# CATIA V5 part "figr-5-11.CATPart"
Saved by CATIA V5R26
Part number: Part1
Bounding box of the stored display mesh (mm): x 0 to 150, y -70 to 70, z -150 to 69.804
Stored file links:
  D:\_Deepak\CATIA\CATIA V5-6R2016_Deepak\Resources\Part files\Partfiles\c05_catia_v5_6r2016_prt\figr-5-11.CATPart
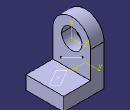
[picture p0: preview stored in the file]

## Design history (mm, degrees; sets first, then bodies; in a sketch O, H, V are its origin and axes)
Set1
  Sketch1 on face of Pad2, origin (0, 0, -100), H (1, 0, 0), V (0, 1, 0)
    point P1 (100, 0)
    coincidence: P1 H
  Sketch2 on face of Pad1, origin (50, 0, 0), H (0, 1, 0), V (0, 0, 1)
    line L1 (-40, -80) -> (40, -40)
  Plane1: type 1Line1Pt, RefPoint Sketch1, Line Sketch2
Body1 (main body)
  Sketch3 on yz-plane, origin (0, 0, 0), H (0, 1, 0), V (0, 0, 1)
    arc A1 centre (0, 0) radius 70 from (70, 0) to (-70, 0) ccw
    point P1 (70, 0)
    point P2 (-70, 0)
    line L1 (-70, 0) -> (-70, -150)
    line L2 (-70, -150) -> (70, -150)
    line L3 (70, -150) -> (70, 0)
    circle A2 centre (0, 0) radius 37.5
    radius A1 = 70
    radius A2 = 37.5
    distance O L2 = 150
    coincidence: P1 H, P2 H
    tangency: L1 A1, L3 A1
    horizontal: L2 H
  Pad1: profile Sketch3, direction (1, 0, 0), length 50
  Sketch4 on face of Pad1, origin (50, 0, 0), H (0, 1, 0), V (0, 0, 1)
    line L1 (-70, -150) -> (70, -150)
    line L2 (70, -150) -> (70, -100)
    line L3 (70, -100) -> (-70, -100)
    line L4 (-70, -100) -> (-70, -150)
    reference projected line E1 (-70, -150) -> (70, -150) from edge [face of Pad1 | face of Pad1]
    reference projected line E2 (-70, 0) -> (-70, -150) from edge [face of Pad1 | face of Pad1]
    reference projected line E3 (70, -150) -> (70, 0) from edge [face of Pad1 | face of Pad1]
    length L2 = 50
    horizontal: L1 H, L3 H
    vertical: L2 V, L4 V
    coincidence: L1 E1, E2 L4, L2 E3
  Pad2: profile Sketch4, direction (1, 0, 0), length 100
